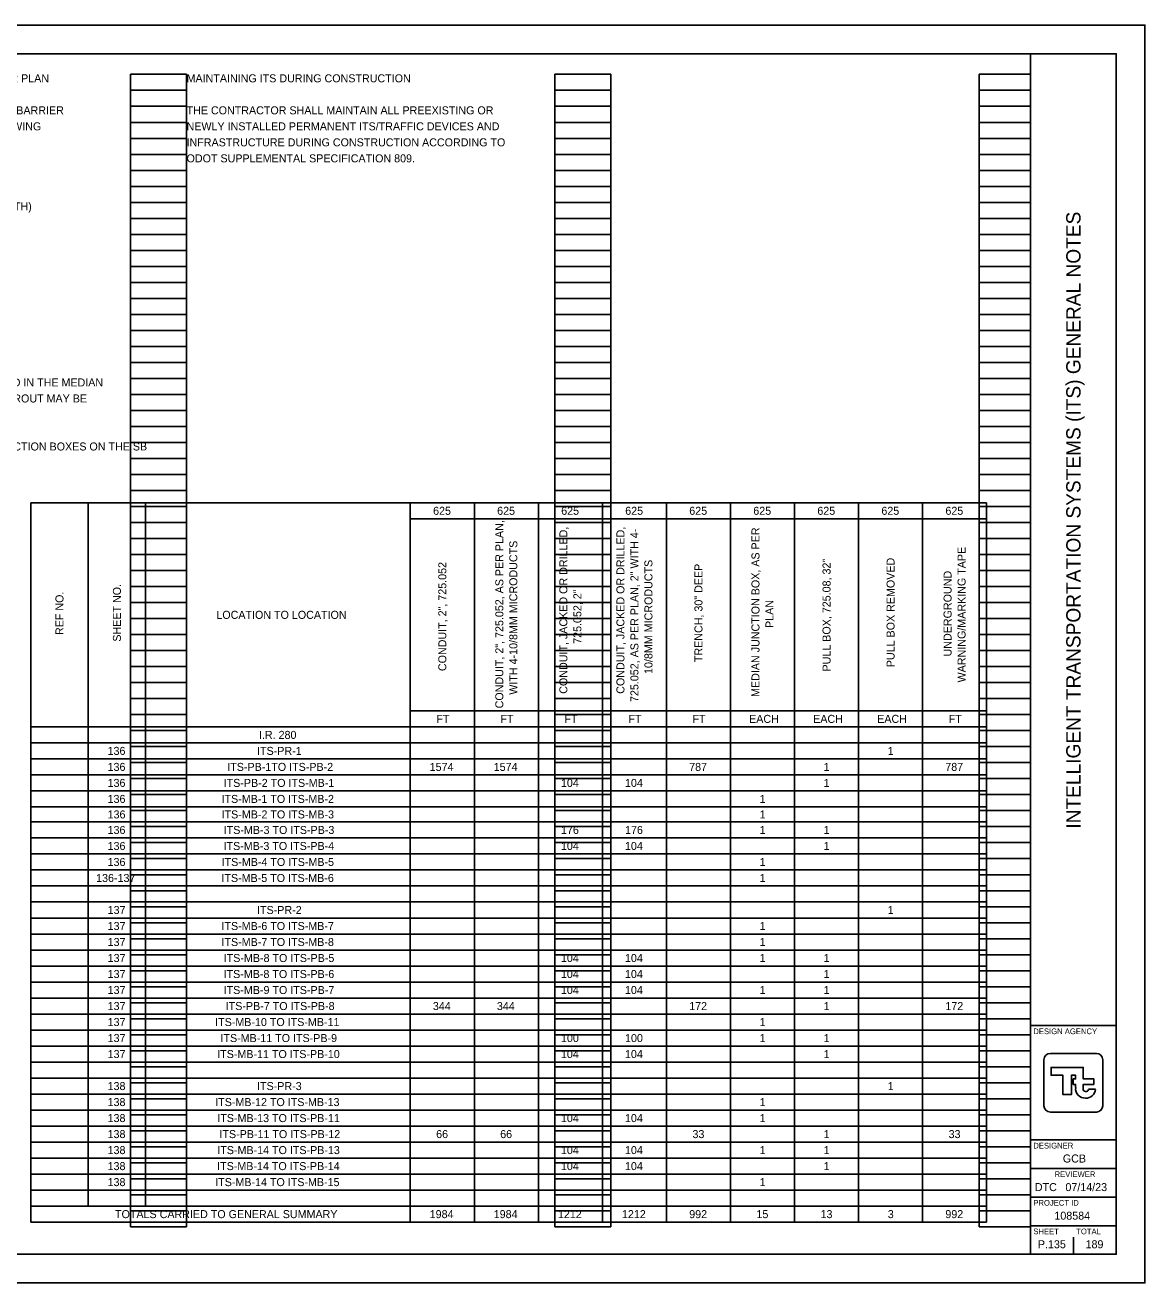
# Model space of a CAD drawing. Extents: x 0 to 34, y 0 to 22.
# Drawn here: x 14.42 to 34, y 0 to 22 of the extents above; entities that cross this region are included whole.
import ezdxf

# ---------------------------------------------------------------- set-up
doc = ezdxf.new("R2010")
doc.units = 0
for name, color, linetype in [('SH_Border', 7, 'Continuous'), ('SH_Cut_Line', 7, 'Continuous'), ('SH_Data', 7, 'Continuous'), ('SH_Text', 7, 'Continuous')]:
    doc.layers.add(name, color=color, linetype=linetype)

msp = doc.modelspace()

# ---------------------------------------------------------------- linework, layer by layer
at = {"layer": 'SH_Border'}
for p, q in [((32, 0.5), (32, 21.5)), ((32, 4.5), (33.5, 4.5)), ((32, 2.5), (33.5, 2.5)), ((32, 2), (33.5, 2)), ((32, 1.5), (33.5, 1.5)), ((32, 1), (33.5, 1))]:
    msp.add_line(p, q, dxfattribs=at)
msp.add_lwpolyline([(1.5, 21.5), (33.5, 21.5), (33.5, 0.5), (1.5, 0.5)], close=True, dxfattribs=at)
at = {"layer": 'SH_Cut_Line'}
msp.add_lwpolyline([(0, 0), (34, 0), (34, 22), (0, 22)], close=True, dxfattribs=at)
at = {"layer": 'SH_Data'}
for p, q in [((16.26, 0.98), (16.26, 21.14)), ((16.26, 21.14), (17.24, 21.14)), ((17.24, 0.98), (17.24, 21.14)), ((23.68, 0.98), (23.68, 21.14)), ((23.68, 21.14), (24.66, 21.14)), ((24.66, 0.98), (24.66, 21.14)), ((31.1, 0.98), (31.1, 21.14)), ((31.1, 21.14), (32, 21.14)), ((32, 0.98), (32, 21.14)), ((16.26, 20.86), (17.24, 20.86)), ((23.68, 20.86), (24.66, 20.86)), ((31.1, 20.86), (32, 20.86)), ((16.26, 20.58), (17.24, 20.58)), ((23.68, 20.58), (24.66, 20.58)), ((31.1, 20.58), (32, 20.58)), ((16.26, 20.3), (17.24, 20.3)), ((23.68, 20.3), (24.66, 20.3)), ((31.1, 20.3), (32, 20.3)), ((16.26, 20.02), (17.24, 20.02)), ((23.68, 20.02), (24.66, 20.02)), ((31.1, 20.02), (32, 20.02)), ((16.26, 19.74), (17.24, 19.74)), ((23.68, 19.74), (24.66, 19.74)), ((31.1, 19.74), (32, 19.74)), ((16.26, 19.46), (17.24, 19.46)), ((23.68, 19.46), (24.66, 19.46)), ((31.1, 19.46), (32, 19.46)), ((16.26, 19.18), (17.24, 19.18)), ((23.68, 19.18), (24.66, 19.18)), ((31.1, 19.18), (32, 19.18)), ((16.26, 18.9), (17.24, 18.9)), ((23.68, 18.9), (24.66, 18.9)), ((31.1, 18.9), (32, 18.9)), ((16.26, 18.62), (17.24, 18.62)), ((23.68, 18.62), (24.66, 18.62)), ((31.1, 18.62), (32, 18.62)), ((16.26, 18.34), (17.24, 18.34)), ((23.68, 18.34), (24.66, 18.34)), ((31.1, 18.34), (32, 18.34)), ((16.26, 18.06), (17.24, 18.06)), ((23.68, 18.06), (24.66, 18.06)), ((31.1, 18.06), (32, 18.06)), ((16.26, 17.78), (17.24, 17.78)), ((23.68, 17.78), (24.66, 17.78)), ((31.1, 17.78), (32, 17.78)), ((16.26, 17.5), (17.24, 17.5)), ((23.68, 17.5), (24.66, 17.5)), ((31.1, 17.5), (32, 17.5)), ((16.26, 17.22), (17.24, 17.22)), ((23.68, 17.22), (24.66, 17.22)), ((31.1, 17.22), (32, 17.22)), ((16.26, 16.94), (17.24, 16.94)), ((23.68, 16.94), (24.66, 16.94)), ((31.1, 16.94), (32, 16.94)), ((16.26, 16.66), (17.24, 16.66)), ((23.68, 16.66), (24.66, 16.66)), ((31.1, 16.66), (32, 16.66)), ((16.26, 16.38), (17.24, 16.38)), ((23.68, 16.38), (24.66, 16.38)), ((31.1, 16.38), (32, 16.38)), ((16.26, 16.1), (17.24, 16.1)), ((23.68, 16.1), (24.66, 16.1)), ((31.1, 16.1), (32, 16.1)), ((16.26, 15.82), (17.24, 15.82)), ((23.68, 15.82), (24.66, 15.82)), ((31.1, 15.82), (32, 15.82)), ((16.26, 15.54), (17.24, 15.54)), ((23.68, 15.54), (24.66, 15.54)), ((31.1, 15.54), (32, 15.54)), ((16.26, 15.26), (17.24, 15.26)), ((23.68, 15.26), (24.66, 15.26)), ((31.1, 15.26), (32, 15.26)), ((16.26, 14.98), (17.24, 14.98)), ((23.68, 14.98), (24.66, 14.98)), ((31.1, 14.98), (32, 14.98)), ((16.26, 14.7), (17.24, 14.7)), ((23.68, 14.7), (24.66, 14.7)), ((31.1, 14.7), (32, 14.7)), ((16.26, 14.42), (17.24, 14.42)), ((23.68, 14.42), (24.66, 14.42)), ((31.1, 14.42), (32, 14.42)), ((16.26, 14.14), (17.24, 14.14)), ((23.68, 14.14), (24.66, 14.14)), ((31.1, 14.14), (32, 14.14)), ((16.26, 13.86), (17.24, 13.86)), ((23.68, 13.86), (24.66, 13.86)), ((31.1, 13.86), (32, 13.86)), ((16.26, 13.58), (17.24, 13.58)), ((23.68, 13.58), (24.66, 13.58)), ((31.1, 13.58), (32, 13.58)), ((16.26, 13.3), (17.24, 13.3)), ((23.68, 13.3), (24.66, 13.3)), ((31.1, 13.3), (32, 13.3)), ((16.26, 13.02), (17.24, 13.02)), ((23.68, 13.02), (24.66, 13.02)), ((31.1, 13.02), (32, 13.02)), ((16.26, 12.74), (17.24, 12.74)), ((23.68, 12.74), (24.66, 12.74)), ((31.1, 12.74), (32, 12.74)), ((16.26, 12.46), (17.24, 12.46)), ((23.68, 12.46), (24.66, 12.46)), ((31.1, 12.46), (32, 12.46)), ((16.26, 12.18), (17.24, 12.18)), ((23.68, 12.18), (24.66, 12.18)), ((31.1, 12.18), (32, 12.18)), ((16.26, 11.9), (17.24, 11.9)), ((23.68, 11.9), (24.66, 11.9)), ((31.1, 11.9), (32, 11.9)), ((16.26, 11.62), (17.24, 11.62)), ((23.68, 11.62), (24.66, 11.62)), ((31.1, 11.62), (32, 11.62)), ((16.26, 11.34), (17.24, 11.34)), ((23.68, 11.34), (24.66, 11.34)), ((31.1, 11.34), (32, 11.34)), ((16.26, 11.06), (17.24, 11.06)), ((23.68, 11.06), (24.66, 11.06)), ((31.1, 11.06), (32, 11.06)), ((16.26, 10.78), (17.24, 10.78)), ((23.68, 10.78), (24.66, 10.78)), ((31.1, 10.78), (32, 10.78)), ((16.26, 10.5), (17.24, 10.5)), ((23.68, 10.5), (24.66, 10.5)), ((31.1, 10.5), (32, 10.5)), ((16.26, 10.22), (17.24, 10.22)), ((23.68, 10.22), (24.66, 10.22)), ((31.1, 10.22), (32, 10.22)), ((16.26, 9.94), (17.24, 9.94)), ((23.68, 9.94), (24.66, 9.94)), ((31.1, 9.94), (32, 9.94)), ((16.26, 9.66), (17.24, 9.66)), ((23.68, 9.66), (24.66, 9.66)), ((31.1, 9.66), (32, 9.66)), ((16.26, 9.38), (17.24, 9.38)), ((23.68, 9.38), (24.66, 9.38)), ((31.1, 9.38), (32, 9.38)), ((16.26, 9.1), (17.24, 9.1)), ((23.68, 9.1), (24.66, 9.1)), ((31.1, 9.1), (32, 9.1)), ((16.26, 8.82), (17.24, 8.82)), ((23.68, 8.82), (24.66, 8.82)), ((31.1, 8.82), (32, 8.82)), ((16.26, 8.54), (17.24, 8.54)), ((23.68, 8.54), (24.66, 8.54)), ((31.1, 8.54), (32, 8.54)), ((16.26, 8.26), (17.24, 8.26)), ((23.68, 8.26), (24.66, 8.26)), ((31.1, 8.26), (32, 8.26)), ((16.26, 7.98), (17.24, 7.98)), ((23.68, 7.98), (24.66, 7.98)), ((31.1, 7.98), (32, 7.98)), ((16.26, 7.7), (17.24, 7.7)), ((23.68, 7.7), (24.66, 7.7)), ((31.1, 7.7), (32, 7.7)), ((16.26, 7.42), (17.24, 7.42)), ((23.68, 7.42), (24.66, 7.42)), ((31.1, 7.42), (32, 7.42)), ((16.26, 7.14), (17.24, 7.14)), ((23.68, 7.14), (24.66, 7.14)), ((31.1, 7.14), (32, 7.14)), ((16.26, 6.86), (17.24, 6.86)), ((23.68, 6.86), (24.66, 6.86)), ((31.1, 6.86), (32, 6.86)), ((16.26, 6.58), (17.24, 6.58)), ((23.68, 6.58), (24.66, 6.58)), ((31.1, 6.58), (32, 6.58)), ((16.26, 6.3), (17.24, 6.3)), ((23.68, 6.3), (24.66, 6.3)), ((31.1, 6.3), (32, 6.3)), ((16.26, 6.02), (17.24, 6.02)), ((23.68, 6.02), (24.66, 6.02)), ((31.1, 6.02), (32, 6.02)), ((16.26, 5.74), (17.24, 5.74)), ((23.68, 5.74), (24.66, 5.74)), ((31.1, 5.74), (32, 5.74)), ((16.26, 5.46), (17.24, 5.46)), ((23.68, 5.46), (24.66, 5.46)), ((31.1, 5.46), (32, 5.46)), ((16.26, 5.18), (17.24, 5.18)), ((23.68, 5.18), (24.66, 5.18)), ((31.1, 5.18), (32, 5.18)), ((16.26, 4.9), (17.24, 4.9)), ((23.68, 4.9), (24.66, 4.9)), ((31.1, 4.9), (32, 4.9)), ((16.26, 4.62), (17.24, 4.62)), ((23.68, 4.62), (24.66, 4.62)), ((31.1, 4.62), (32, 4.62)), ((16.26, 4.34), (17.24, 4.34)), ((23.68, 4.34), (24.66, 4.34)), ((31.1, 4.34), (32, 4.34)), ((16.26, 4.06), (17.24, 4.06)), ((23.68, 4.06), (24.66, 4.06)), ((31.1, 4.06), (32, 4.06)), ((16.26, 3.78), (17.24, 3.78)), ((23.68, 3.78), (24.66, 3.78)), ((31.1, 3.78), (32, 3.78)), ((16.26, 3.5), (17.24, 3.5)), ((23.68, 3.5), (24.66, 3.5)), ((31.1, 3.5), (32, 3.5)), ((32.75, 3.5), (32.75, 3.5)), ((32.791, 3.415), (32.791, 3.415)), ((33.136, 3.385), (33.015, 3.385)), ((16.26, 3.22), (17.24, 3.22)), ((23.68, 3.22), (24.66, 3.22)), ((31.1, 3.22), (32, 3.22)), ((16.26, 2.94), (17.24, 2.94)), ((23.68, 2.94), (24.66, 2.94)), ((31.1, 2.94), (32, 2.94)), ((16.26, 2.66), (17.24, 2.66)), ((23.68, 2.66), (24.66, 2.66)), ((31.1, 2.66), (32, 2.66)), ((16.26, 2.38), (17.24, 2.38)), ((23.68, 2.38), (24.66, 2.38)), ((31.1, 2.38), (32, 2.38)), ((16.26, 2.1), (17.24, 2.1)), ((23.68, 2.1), (24.66, 2.1)), ((31.1, 2.1), (32, 2.1)), ((16.26, 1.82), (17.24, 1.82)), ((23.68, 1.82), (24.66, 1.82)), ((31.1, 1.82), (32, 1.82)), ((16.26, 1.54), (17.24, 1.54)), ((23.68, 1.54), (24.66, 1.54)), ((31.1, 1.54), (32, 1.54)), ((16.26, 1.26), (17.24, 1.26)), ((23.68, 1.26), (24.66, 1.26)), ((31.1, 1.26), (32, 1.26)), ((16.26, 0.98), (17.24, 0.98)), ((23.68, 0.98), (24.66, 0.98)), ((31.1, 0.98), (32, 0.98)), ((32.375, 0.675), (32.375, 0.675)), ((32.75, 0.5), (32.75, 0.8))]:
    msp.add_line(p, q, dxfattribs=at)
for points in [[(32.348, 4.014), (33.152, 4.014)], [(32.236, 3.099), (32.236, 3.901)], [(32.922, 3.399), (32.922, 3.47), (33.107, 3.47), (33.107, 3.568), (32.922, 3.568), (32.922, 3.768), (32.361, 3.768), (32.361, 3.632), (32.566, 3.632), (32.566, 3.294), (32.715, 3.294), (32.715, 3.63), (32.79, 3.63), (32.79, 3.568), (32.748, 3.568), (32.748, 3.47), (32.79, 3.47), (32.79, 3.415), (32.791, 3.415)], [(33.264, 3.901), (33.264, 3.099)], [(33.152, 2.986), (32.348, 2.986)]]:
    msp.add_lwpolyline(points, dxfattribs=at)
for centre, radius, start, end in [((32.348, 3.901), 0.113, 90, 180), ((33.152, 3.901), 0.113, 360, 90), ((32.949, 3.392), 0.16, 171.8856, 274.8323), ((32.968, 3.392), 0.0473, 171.8856, 350.9243), ((32.976, 3.392), 0.16, 265.1677, 357.3201), ((32.348, 3.099), 0.113, 180, 270), ((33.152, 3.099), 0.113, 270, 360)]:
    msp.add_arc(centre, radius, start, end, dxfattribs=at)
at = {"layer": 'SH_Text'}
for p, q in [((14.515, 13.645), (31.233, 13.645)), ((14.515, 13.645), (14.515, 1.062)), ((15.52, 13.645), (15.52, 1.342)), ((16.524, 13.645), (16.524, 1.342)), ((21.153, 13.645), (21.153, 1.062)), ((22.273, 13.645), (22.273, 1.062)), ((23.393, 13.645), (23.393, 1.062)), ((24.513, 13.645), (24.513, 1.062)), ((25.633, 13.645), (25.633, 1.062)), ((26.753, 13.645), (26.753, 1.062)), ((27.873, 13.645), (27.873, 1.062)), ((28.993, 13.645), (28.993, 1.062)), ((30.113, 13.645), (30.113, 1.062)), ((31.233, 13.645), (31.233, 1.062)), ((21.153, 13.365), (31.233, 13.365)), ((21.153, 10.005), (31.233, 10.005)), ((14.515, 9.725), (31.233, 9.725)), ((14.515, 9.445), (31.233, 9.445)), ((14.515, 9.165), (31.233, 9.165)), ((14.515, 8.885), (31.233, 8.885)), ((14.515, 8.605), (31.233, 8.605)), ((14.515, 8.325), (31.233, 8.325)), ((14.515, 8.062), (31.233, 8.062)), ((14.515, 7.782), (31.233, 7.782)), ((14.515, 7.502), (31.233, 7.502)), ((14.515, 7.222), (31.233, 7.222)), ((14.515, 6.942), (31.233, 6.942)), ((14.515, 6.662), (31.233, 6.662)), ((14.515, 6.382), (31.233, 6.382)), ((14.515, 6.102), (31.233, 6.102)), ((14.515, 5.822), (31.233, 5.822)), ((14.515, 5.542), (31.233, 5.542)), ((14.515, 5.262), (31.233, 5.262)), ((14.515, 4.982), (31.233, 4.982)), ((14.515, 4.702), (31.233, 4.702)), ((14.515, 4.422), (31.233, 4.422)), ((14.515, 4.142), (31.233, 4.142)), ((14.515, 3.862), (31.233, 3.862)), ((14.515, 3.582), (31.233, 3.582)), ((14.515, 3.302), (31.233, 3.302)), ((14.515, 3.022), (31.233, 3.022)), ((14.515, 2.742), (31.233, 2.742)), ((14.515, 2.462), (31.233, 2.462)), ((14.515, 2.182), (31.233, 2.182)), ((14.515, 1.902), (31.233, 1.902)), ((14.515, 1.622), (31.233, 1.622)), ((14.515, 1.342), (31.233, 1.342)), ((14.515, 1.062), (31.233, 1.062))]:
    msp.add_line(p, q, dxfattribs=at)

# ---------------------------------------------------------------- texts
at = {"layer": 'SH_Data'}
msp.add_text('INTELLIGENT TRANSPORTATION SYSTEMS (ITS) GENERAL NOTES', height=0.25, rotation=90, dxfattribs=at).set_placement((32.875, 7.945))
for s, height, p in [('DESIGN AGENCY', 0.1, (32.05, 4.35)), ('DESIGNER', 0.1, (32.05, 2.35)), ('GCB', 0.14, (32.566, 2.105)), ('REVIEWER', 0.1, (32.422, 1.85)), ('DTC', 0.14, (32.076, 1.605)), ('07/14/23', 0.14, (32.611, 1.605)), ('PROJECT ID', 0.1, (32.05, 1.35)), ('108584', 0.14, (32.418, 1.105)), ('SHEET', 0.1, (32.05, 0.85)), ('TOTAL', 0.1, (32.8, 0.85)), ('P.135', 0.14, (32.129, 0.605)), ('189', 0.14, (32.963, 0.605))]:
    msp.add_text(s, height=height, dxfattribs=at).set_placement(p)
at = {"layer": 'SH_Text'}
for s, p in [('ITEM 625E29931 MEDIAN JUNCTION BOX, AS PER PLAN', (9.82, 21)), ('MAINTAINING ITS DURING CONSTRUCTION', (17.24, 21)), ('THE CONTRACTOR SHALL SUPPLY THE MEDIAN BARRIER', (9.82, 20.44)), ('THE CONTRACTOR SHALL MAINTAIN ALL PREEXISTING OR', (17.24, 20.44)), ('JUNCTION PULL BOXES THAT MEET THE FOLLOWING', (9.82, 20.16)), ('NEWLY INSTALLED PERMANENT ITS/TRAFFIC DEVICES AND', (17.24, 20.16)), ('INFRASTRUCTURE DURING CONSTRUCTION ACCORDING TO', (17.24, 19.88)), ('ODOT SUPPLEMENTAL SPECIFICATION 809.', (17.24, 19.6)), ('    SIZE: 17 INCHES (HEIGHT) X 30 INCHES (LENGTH)', (9.82, 18.76)), ('THE MEDIAN JUNCTION BOX SHALL BE SECURED IN THE MEDIAN', (9.82, 15.68)), ('BARRIER WALL USING DOWELS. (NONSHRINK GROUT MAY BE', (9.82, 15.4)), ('THE CONTRACTOR SHALL INSTALL THE ITS JUNCTION BOXES ON THE SB', (9.82, 14.56)), ('625', (21.552, 13.435)), ('625', (22.672, 13.435)), ('625', (23.792, 13.435)), ('625', (24.912, 13.435)), ('625', (26.032, 13.435)), ('625', (27.152, 13.435)), ('625', (28.272, 13.435)), ('625', (29.392, 13.435)), ('625', (30.512, 13.435)), ('LOCATION TO LOCATION', (17.761, 11.615)), ('FT', (21.609, 9.795)), ('FT', (22.729, 9.795)), ('FT', (23.849, 9.795)), ('FT', (24.969, 9.795)), ('FT', (26.089, 9.795)), ('EACH', (27.079, 9.795)), ('EACH', (28.199, 9.795)), ('EACH', (29.319, 9.795)), ('FT', (30.569, 9.795)), ('I.R. 280', (18.506, 9.515)), ('136', (15.859, 9.235)), ('ITS-PR-1', (18.473, 9.235)), ('1', (29.503, 9.235)), ('136', (15.859, 8.955)), ('ITS-PB-1TO ITS-PB-2', (17.952, 8.955)), ('1574', (21.492, 8.955)), ('1574', (22.612, 8.955)), ('787', (26.03, 8.955)), ('1', (28.383, 8.955)), ('787', (30.51, 8.955)), ('136', (15.859, 8.675)), ('ITS-PB-2 TO ITS-MB-1', (17.889, 8.675)), ('104', (23.788, 8.675)), ('104', (24.908, 8.675)), ('1', (28.383, 8.675)), ('136', (15.859, 8.395)), ('ITS-MB-1 TO ITS-MB-2', (17.852, 8.395)), ('1', (27.263, 8.395)), ('136', (15.859, 8.124)), ('ITS-MB-2 TO ITS-MB-3', (17.853, 8.124)), ('1', (27.263, 8.124)), ('136', (15.859, 7.852)), ('ITS-MB-3 TO ITS-PB-3', (17.89, 7.852)), ('176', (23.789, 7.852)), ('176', (24.909, 7.852)), ('1', (27.263, 7.852)), ('1', (28.383, 7.852)), ('136', (15.859, 7.572)), ('ITS-MB-3 TO ITS-PB-4', (17.887, 7.572)), ('104', (23.788, 7.572)), ('104', (24.908, 7.572)), ('1', (28.383, 7.572)), ('136', (15.859, 7.292)), ('ITS-MB-4 TO ITS-MB-5', (17.853, 7.292)), ('1', (27.263, 7.292)), ('136-137', (15.658, 7.012)), ('ITS-MB-5 TO ITS-MB-6', (17.85, 7.012)), ('1', (27.263, 7.012)), ('137', (15.86, 6.452)), ('ITS-PR-2', (18.473, 6.452)), ('1', (29.503, 6.452)), ('137', (15.86, 6.172)), ('ITS-MB-6 TO ITS-MB-7', (17.851, 6.172)), ('1', (27.263, 6.172)), ('137', (15.86, 5.892)), ('ITS-MB-7 TO ITS-MB-8', (17.851, 5.892)), ('1', (27.263, 5.892)), ('137', (15.86, 5.612)), ('ITS-MB-8 TO ITS-PB-5', (17.89, 5.612)), ('104', (23.788, 5.612)), ('104', (24.908, 5.612)), ('1', (27.263, 5.612)), ('1', (28.383, 5.612)), ('137', (15.86, 5.332)), ('ITS-MB-8 TO ITS-PB-6', (17.888, 5.332)), ('104', (23.788, 5.332)), ('104', (24.908, 5.332)), ('1', (28.383, 5.332)), ('137', (15.86, 5.052)), ('ITS-MB-9 TO ITS-PB-7', (17.889, 5.052)), ('104', (23.788, 5.052)), ('104', (24.908, 5.052)), ('1', (27.263, 5.052)), ('1', (28.383, 5.052)), ('137', (15.86, 4.772)), ('ITS-PB-7 TO ITS-PB-8', (17.925, 4.772)), ('344', (21.548, 4.772)), ('344', (22.668, 4.772)), ('172', (26.031, 4.772)), ('1', (28.383, 4.772)), ('172', (30.511, 4.772)), ('137', (15.86, 4.492)), ('ITS-MB-10 TO ITS-MB-11', (17.74, 4.492)), ('1', (27.263, 4.492)), ('137', (15.86, 4.212)), ('ITS-MB-11 TO ITS-PB-9', (17.833, 4.212)), ('100', (23.789, 4.212)), ('100', (24.909, 4.212)), ('1', (27.263, 4.212)), ('1', (28.383, 4.212)), ('137', (15.86, 3.932)), ('ITS-MB-11 TO ITS-PB-10', (17.776, 3.932)), ('104', (23.788, 3.932)), ('104', (24.908, 3.932)), ('1', (28.383, 3.932)), ('138', (15.859, 3.372)), ('ITS-PR-3', (18.473, 3.372)), ('1', (29.503, 3.372)), ('138', (15.859, 3.092)), ('ITS-MB-12 TO ITS-MB-13', (17.741, 3.092)), ('1', (27.263, 3.092)), ('138', (15.859, 2.812)), ('ITS-MB-13 TO ITS-PB-11', (17.778, 2.812)), ('104', (23.788, 2.812)), ('104', (24.908, 2.812)), ('1', (27.263, 2.812)), ('138', (15.859, 2.532)), ('ITS-PB-11 TO ITS-PB-12', (17.815, 2.532)), ('66', (21.605, 2.532)), ('66', (22.725, 2.532)), ('33', (26.088, 2.532)), ('1', (28.383, 2.532)), ('33', (30.568, 2.532)), ('138', (15.859, 2.252)), ('ITS-MB-14 TO ITS-PB-13', (17.778, 2.252)), ('104', (23.788, 2.252)), ('104', (24.908, 2.252)), ('1', (27.263, 2.252)), ('1', (28.383, 2.252)), ('138', (15.859, 1.972)), ('ITS-MB-14 TO ITS-PB-14', (17.775, 1.972)), ('104', (23.788, 1.972)), ('104', (24.908, 1.972)), ('1', (28.383, 1.972)), ('138', (15.859, 1.692)), ('ITS-MB-14 TO ITS-MB-15', (17.741, 1.692)), ('1', (27.263, 1.692)), ('TOTALS CARRIED TO GENERAL SUMMARY', (15.989, 1.132)), ('1984', (21.492, 1.132)), ('1984', (22.612, 1.132)), ('1212', (23.735, 1.132)), ('1212', (24.855, 1.132)), ('992', (26.031, 1.132)), ('15', (27.207, 1.132)), ('13', (28.328, 1.132)), ('3', (29.504, 1.132)), ('992', (30.511, 1.132))]:
    msp.add_text(s, height=0.14, dxfattribs=at).set_placement(p)
for s, p in [('CONDUIT, 2", 725.052, AS PER PLAN, ', (22.78, 10.049)), ('CONDUIT, JACKED OR DRILLED, ', (23.9, 10.304)), ('CONDUIT, JACKED OR DRILLED, ', (24.898, 10.304)), ('MEDIAN JUNCTION BOX, AS PER ', (27.26, 10.249)), ('725.052, AS PER PLAN, 2" WITH 4-', (25.143, 10.16)), ('WITH 4-10/8MM MICRODUCTS', (23.025, 10.288)), ('WARNING/MARKING TAPE', (30.865, 10.503)), ('CONDUIT, 2", 725.052', (21.783, 10.701)), ('10/8MM MICRODUCTS', (25.388, 10.651)), ('TRENCH, 30" DEEP', (26.263, 10.858)), ('PULL BOX, 725.08, 32"', (28.503, 10.694)), ('PULL BOX REMOVED', (29.623, 10.769)), ('UNDERGROUND ', (30.62, 10.957)), ('SHEET NO.', (16.092, 11.216)), ('725.052, 2"', (24.145, 11.178)), ('REF NO.', (15.087, 11.332)), ('PLAN', (27.505, 11.456))]:
    msp.add_text(s, height=0.14, rotation=90, dxfattribs=at).set_placement(p)

doc.saveas('drawing.dxf')
